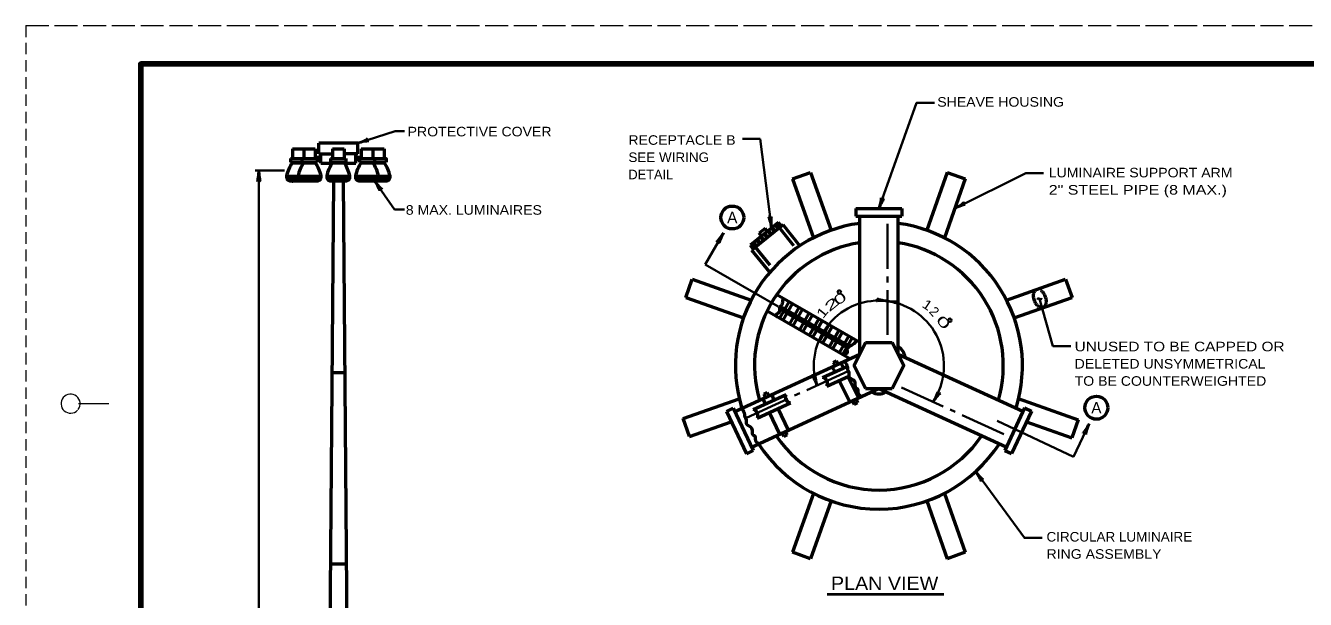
# Model space of a CAD drawing. Extents: x -1 to 679, y 0 to 440.
# Drawn here: x -1.5 to 332.8, y 289.7 to 439.6 of the extents above; entities that cross this region are included whole.
import ezdxf
from ezdxf.enums import TextEntityAlignment as Align

# ---------------------------------------------------------------- set-up
doc = ezdxf.new("R2010")
doc.units = 0
doc.header["$PDMODE"] = 32
doc.header["$PDSIZE"] = 0.5
doc.linetypes.add('LONG_DASHED', pattern=[7.5, 6, -1.5])
doc.linetypes.add('MEDIUM_DASHED', pattern=[4.5, 3, -1.5])
doc.layers.add('1', color=7, linetype='Continuous', lineweight=35)
doc.layers.add('61', color=7, linetype='Continuous', lineweight=35)

msp = doc.modelspace()

# ---------------------------------------------------------------- linework, layer by layer
at = {"layer": '1', "linetype": 'MEDIUM_DASHED', "lineweight": 13}
msp.add_line((-1.425, 439.645), (-1.485, -0.395), dxfattribs=at)
at = {"layer": '1', "lineweight": 53}
for p, q in [((75.106, 406.179), (75.106, 408.929)), ((67.696, 404.929), (71.696, 404.929)), ((67.696, 404.929), (67.696, 403.929)), ((68.196, 407.429), (71.196, 407.429)), ((68.196, 407.429), (68.196, 404.929)), ((70.696, 404.929), (74.696, 404.929)), ((70.696, 404.929), (70.696, 403.929)), ((71.196, 407.429), (74.196, 407.429)), ((71.196, 407.429), (71.196, 404.929)), ((71.196, 407.429), (71.196, 404.929)), ((74.196, 407.429), (74.196, 404.929)), ((74.696, 404.929), (74.696, 403.929)), ((75.106, 406.179), (78.696, 406.179)), ((75.606, 403.679), (75.606, 406.179)), ((78.196, 404.929), (82.196, 404.929)), ((78.196, 404.929), (78.196, 403.929)), ((78.696, 407.429), (81.696, 407.429)), ((78.696, 407.429), (78.696, 404.929)), ((81.696, 407.429), (81.696, 404.929)), ((85.285, 406.179), (81.696, 406.179)), ((82.196, 404.929), (82.196, 403.929)), ((84.785, 403.679), (84.785, 406.179)), ((85.696, 404.929), (89.696, 404.929)), ((85.696, 404.929), (85.696, 403.929)), ((86.196, 407.429), (89.196, 407.429)), ((86.196, 407.429), (86.196, 404.929)), ((89.196, 407.429), (89.196, 404.929)), ((89.196, 407.429), (92.196, 407.429)), ((89.196, 407.429), (89.196, 404.929)), ((89.696, 404.929), (89.696, 403.929)), ((92.196, 407.429), (92.196, 404.929)), ((67.696, 403.929), (71.696, 403.929)), ((68.196, 403.804), (71.196, 403.804)), ((70.696, 403.929), (74.696, 403.929)), ((71.196, 403.804), (74.196, 403.804)), ((75.606, 403.679), (78.606, 403.679)), ((78.196, 403.929), (82.196, 403.929)), ((78.696, 403.804), (81.696, 403.804)), ((81.785, 403.679), (84.785, 403.679)), ((85.696, 403.929), (89.696, 403.929)), ((86.196, 403.804), (89.196, 403.804)), ((88.696, 403.929), (92.696, 403.929)), ((89.196, 403.804), (92.196, 403.804)), ((198.868, 399.594), (203.582, 401.261)), ((203.582, 401.261), (208.916, 386.176)), ((239.249, 401.261), (233.915, 386.176)), ((239.249, 401.261), (243.963, 399.594)), ((66.321, 400.304), (72.196, 400.304)), ((67.884, 400.304), (68.38, 399.064)), ((68.696, 400.304), (69.196, 399.054)), ((69.696, 400.304), (75.196, 400.304)), ((70.196, 400.304), (70.583, 399.066)), ((70.583, 399.066), (74.696, 399.054)), ((70.884, 400.304), (71.38, 399.064)), ((71.696, 400.304), (72.196, 399.054)), ((72.196, 400.304), (73.196, 400.304)), ((72.696, 400.304), (72.696, 399.054)), ((73.696, 400.304), (73.196, 399.054)), ((74.455, 400.304), (73.956, 399.056)), ((75.196, 400.304), (74.808, 399.066)), ((75.196, 400.304), (76.071, 400.304)), ((76.821, 400.304), (77.696, 400.304)), ((78.946, 399.063), (76.946, 149.054)), ((77.696, 400.304), (78.083, 399.066)), ((77.696, 400.304), (82.696, 400.304)), ((78.083, 399.066), (82.196, 399.054)), ((78.384, 400.304), (78.88, 399.064)), ((79.196, 400.304), (79.696, 399.054)), ((80.196, 400.304), (80.196, 399.054)), ((81.196, 400.304), (80.696, 399.054)), ((81.446, 399.056), (83.446, 149.054)), ((81.955, 400.304), (81.456, 399.056)), ((82.696, 400.304), (82.308, 399.066)), ((82.696, 400.304), (83.571, 400.304)), ((84.321, 400.304), (85.196, 400.304)), ((85.196, 400.304), (85.583, 399.066)), ((85.196, 400.304), (90.696, 400.304)), ((85.583, 399.066), (89.696, 399.054)), ((85.884, 400.304), (86.358, 399.118)), ((86.696, 400.304), (87.196, 399.054)), ((87.196, 400.304), (88.196, 400.304)), ((87.696, 400.304), (87.696, 399.054)), ((88.696, 400.304), (88.196, 399.054)), ((88.196, 400.304), (93.196, 400.304)), ((88.583, 399.066), (92.696, 399.054)), ((89.455, 400.304), (88.988, 399.137)), ((90.196, 400.304), (89.808, 399.066)), ((91.696, 400.304), (91.196, 399.054)), ((92.455, 400.304), (91.988, 399.137)), ((93.196, 400.304), (92.808, 399.066)), ((93.196, 400.304), (94.071, 400.304)), ((198.868, 399.594), (204.313, 384.194)), ((243.963, 399.594), (238.518, 384.194)), ((215.415, 391.821), (227.415, 391.821)), ((215.415, 391.821), (215.416, 389.821)), ((227.415, 391.821), (227.415, 389.821)), ((195.215, 388.24), (187.832, 382.261)), ((196.002, 387.268), (195.215, 388.24)), ((215.416, 389.821), (227.415, 389.821)), ((226.416, 353.821), (226.416, 389.821)), ((196.39, 387.583), (188.23, 380.975)), ((191.671, 386.656), (190.117, 385.398)), ((190.746, 384.621), (190.117, 385.398)), ((192.3, 385.879), (191.671, 386.656)), ((199.195, 382.133), (195.419, 386.796)), ((200.796, 382.143), (196.39, 387.583)), ((188.619, 381.29), (187.832, 382.261)), ((192.977, 377.099), (189.201, 381.762)), ((192.914, 375.191), (188.23, 380.975)), ((170.975, 368.654), (172.642, 373.368)), ((172.642, 373.368), (188.042, 367.923)), ((254.788, 367.923), (270.189, 373.368)), ((270.189, 373.368), (271.856, 368.654)), ((170.975, 368.654), (186.06, 363.321)), ((216.416, 356.821), (194.715, 369.35)), ((256.771, 363.321), (271.856, 368.654)), ((213.784, 352.61), (192.205, 365.069)), ((197.92, 367.499), (195.439, 363.202)), ((198.786, 366.999), (196.305, 362.702)), ((200.518, 365.999), (198.037, 361.702)), ((201.384, 365.499), (198.903, 361.202)), ((203.116, 364.499), (200.635, 360.202)), ((203.982, 363.999), (201.501, 359.702)), ((205.714, 362.999), (203.233, 358.702)), ((206.58, 362.499), (204.099, 358.202)), ((208.312, 361.499), (205.831, 357.202)), ((209.178, 360.999), (206.697, 356.702)), ((210.91, 359.999), (208.429, 355.702)), ((211.776, 359.499), (209.295, 355.202)), ((213.508, 358.499), (211.027, 354.202)), ((214.374, 357.999), (211.893, 353.701)), ((217.916, 356.821), (224.916, 356.821)), ((183.799, 338.819), (216.416, 353.821)), ((209.464, 351.661), (210.359, 352.108)), ((209.464, 351.661), (209.886, 350.817)), ((210.359, 352.108), (210.795, 351.236)), ((211.477, 351.549), (212.148, 350.207)), ((226.416, 353.821), (259.051, 338.882)), ((78.546, 349.054), (81.846, 349.054)), ((206.695, 347.699), (213.034, 350.614)), ((207.814, 345.462), (213.548, 348.099)), ((209.241, 350.431), (209.875, 349.162)), ((213.266, 347.97), (216.07, 342.362)), ((188.169, 329.529), (221.415, 344.821)), ((210.994, 346.924), (213.834, 341.244)), ((217.916, 344.821), (224.915, 344.821)), ((221.415, 344.821), (254.698, 329.586)), ((170.273, 336.982), (184.928, 342.163)), ((188.526, 339.342), (197.157, 343.312)), ((189.59, 337.079), (198.337, 341.103)), ((191.064, 342.17), (191.706, 340.804)), ((191.317, 343.394), (192.221, 343.819)), ((191.317, 343.394), (191.749, 342.475)), ((192.221, 343.819), (192.657, 342.893)), ((193.326, 343.234), (193.977, 341.849)), ((214.479, 341.631), (214.952, 340.685)), ((215.846, 341.132), (214.952, 340.685)), ((215.388, 342.049), (215.846, 341.132)), ((257.788, 342.204), (273.505, 336.647)), ((181.564, 338.872), (183.374, 339.724)), ((181.564, 338.872), (186.785, 327.773)), ((183.374, 339.724), (188.594, 328.624)), ((192.77, 338.542), (195.433, 332.88)), ((195.041, 339.587), (197.695, 333.944)), ((259.475, 339.788), (254.274, 328.68)), ((261.287, 338.939), (256.085, 327.832)), ((259.475, 339.788), (261.287, 338.939)), ((171.94, 332.268), (170.273, 336.982)), ((171.94, 332.268), (182.855, 336.127)), ((259.971, 336.129), (271.838, 331.933)), ((273.505, 336.647), (271.838, 331.933)), ((196.118, 333.185), (196.538, 332.294)), ((197.442, 332.72), (196.538, 332.294)), ((197.027, 333.603), (197.442, 332.72)), ((186.785, 327.773), (188.594, 328.624)), ((254.274, 328.68), (256.085, 327.832)), ((204.313, 317.448), (198.868, 302.047)), ((208.916, 315.465), (203.582, 300.38)), ((233.915, 315.466), (239.249, 300.381)), ((238.518, 317.448), (243.963, 302.047)), ((203.582, 300.38), (198.868, 302.047)), ((243.963, 302.047), (239.249, 300.381)), ((78.146, 299.054), (82.246, 299.054))]:
    msp.add_line(p, q, dxfattribs=at)
at = {"layer": '1'}
for p, q in [((185.76, 410.106), (190.424, 410.106)), ((193.344, 386.91), (190.424, 410.106)), ((66.113, 401.804), (58.446, 401.804)), ((59.446, 148.054), (59.446, 401.804)), ((223.666, 376.071), (223.666, 387.821)), ((180.807, 385.484), (176.057, 377.257)), ((191.533, 383.649), (190.746, 384.621)), ((192.115, 384.121), (191.329, 385.093)), ((192.504, 384.436), (191.718, 385.407)), ((193.087, 384.908), (192.3, 385.879)), ((193.476, 385.223), (192.689, 386.194)), ((194.059, 385.695), (193.272, 386.666)), ((194.447, 386.009), (193.661, 386.981)), ((195.03, 386.481), (194.243, 387.453)), ((195.419, 386.796), (194.632, 387.768)), ((189.202, 381.762), (188.415, 382.733)), ((189.59, 382.076), (188.803, 383.048)), ((190.173, 382.548), (189.386, 383.52)), ((190.561, 382.863), (189.775, 383.834)), ((191.144, 383.335), (190.357, 384.306)), ((195.11, 366.257), (176.057, 377.257)), ((223.666, 374.071), (223.666, 372.571)), ((223.666, 358.821), (223.666, 370.571)), ((202.587, 344.433), (213.39, 349.402)), ((227.313, 345.146), (238.179, 340.172)), ((186.787, 337.166), (197.59, 342.135)), ((199.407, 342.971), (200.77, 343.597)), ((239.997, 339.339), (241.361, 338.715)), ((243.179, 337.882), (254.046, 332.909)), ((252.346, 336.354), (272.27, 327.024)), ((276.299, 335.628), (272.27, 327.024))]:
    msp.add_line(p, q, dxfattribs=at)
at = {"layer": '1', "lineweight": 106}
for p, q in [((75.606, 404.929), (74.696, 404.929)), ((84.785, 404.929), (85.696, 404.929))]:
    msp.add_line(p, q, dxfattribs=at)
at = {"layer": '1', "lineweight": 200}
msp.add_line((195.631, 365.956), (213.41, 355.691), dxfattribs=at)
at = {"layer": '1', "lineweight": 40}
msp.add_line((207.899, 291.106), (238.388, 291.106), dxfattribs=at)
at = {"layer": '1'}
for points in [[(221.415, 391.821), (231.273, 419.49), (235.936, 419.49)], [(85.285, 408.929), (95.027, 412.036), (97.483, 412.036)], [(89.696, 399.054), (94.903, 391.61), (97.451, 391.61)], [(241.24, 391.894), (259.769, 401.117), (264.432, 401.117)], [(263.365, 368.261), (266.858, 355.942), (271.521, 355.942)], [(246.702, 323.129), (259.408, 305.817), (264.071, 305.817)]]:
    msp.add_lwpolyline(points, dxfattribs=at)
at = {"layer": '1', "lineweight": 53}
for points in [[(85.285, 406.179), (85.285, 408.929), (75.106, 408.929)], [(88.696, 404.929), (92.696, 404.929), (92.696, 403.929)], [(67.196, 400.304), (67.583, 399.066), (71.696, 399.054)], [(216.416, 353.821), (216.416, 387.986), (216.416, 389.821)], [(217.916, 356.821), (214.916, 350.821), (217.916, 344.821)], [(224.915, 344.821), (227.915, 350.821), (224.916, 356.821)]]:
    msp.add_lwpolyline(points, dxfattribs=at)
for centre in [(183.109, 389.517), (278.22, 339.813)]:
    msp.add_circle(centre, 3, dxfattribs=at)
at = {"layer": '1'}
for centre in [(211.087, 370.039), (239.939, 362.669)]:
    msp.add_circle(centre, 0.45, dxfattribs=at)
at = {"layer": '1', "lineweight": 53}
for centre, radius, start, end in [((75.102, 398.772), 8.545, 143.92712, 169.6757), ((78.102, 398.772), 8.545, 143.92712, 169.6757), ((67.289, 398.772), 8.545, 10.3243, 36.07288), ((85.602, 398.772), 8.545, 143.92712, 169.6757), ((74.789, 398.772), 8.545, 10.3243, 36.07288), ((93.102, 398.772), 8.545, 143.92712, 169.6757), ((82.289, 398.772), 8.545, 10.3243, 36.07288), ((85.289, 398.772), 8.545, 10.3243, 36.07288), ((67.758, 400.128), 1.077, 170.6394, 266.68021), ((70.758, 400.128), 1.077, 170.6394, 266.68021), ((74.633, 400.128), 1.077, 273.31979, 9.3606), ((78.258, 400.128), 1.077, 170.6394, 260.64075), ((82.133, 400.128), 1.077, 273.31979, 9.3606), ((85.758, 400.128), 1.077, 170.6394, 266.68021), ((89.633, 400.128), 1.077, 273.31979, 9.3606), ((92.633, 400.128), 1.077, 273.31979, 9.3606), ((221.415, 350.821), 37.5, 97.66187, 197.32332), ((221.415, 350.821), 37.5, 342.77204, 82.33736), ((221.415, 350.821), 32.5, 98.84944, 196.18056), ((221.415, 350.821), 32.5, 343.91337, 81.14967), ((224.68, 352.706), 3.565, 4.53272, 60.86921), ((206.501, 346.226), 1.486, 327.89377, 82.48428), ((198.452, 342.584), 1.486, 150.66912, 265.55469), ((221.414, 346.606), 3.188, 235.2883, 304.81151), ((188.332, 337.869), 1.486, 327.89377, 82.48428), ((221.415, 350.821), 32.5, 214.35563, 325.74061), ((221.415, 350.821), 37.5, 213.05829, 327.03907)]:
    msp.add_arc(centre, radius, start, end, dxfattribs=at)
at = {"layer": '1'}
for centre, radius, start, end in [((221.415, 350.821), 17, 82.39357, 197.72393), ((263.122, 367.999), 0.357, 47.242, 165.78449), ((263.607, 368.523), 0.357, 227.242, 345.78449), ((221.415, 350.821), 17, 326.24589, 82.39357)]:
    msp.add_arc(centre, radius, start, end, dxfattribs=at)
at = {"layer": '1', "lineweight": 40}
for centre, major_axis, ratio, start_param, end_param in [((86.241, 409.523), (-1.654, -0.691), 0.122415, 0.8963533, 3.1415927), ((86.417, 409.067), (-1.727, -0.366), 0.07063, 3.1407148, 5.41811), ((59.234, 400.683), (0.176, 1.756), 0.07063, 3.1407148, 5.41811), ((59.722, 400.712), (-0.156, 1.786), 0.122415, 0.8963533, 3.1415927), ((90.165, 398.014), (0.863, -1.54), 0.07063, 6.2823074, 8.5597026), ((90.548, 398.318), (-1.151, 1.374), 0.122415, 0.8963533, 3.1415927), ((221.521, 392.941), (-0.452, -1.735), 0.122415, 0.8963533, 3.1415927), ((221.521, 392.941), (-0.452, -1.735), 0.122415, 0.8963533, 3.1415927), ((221.991, 392.805), (-0.755, -1.596), 0.07063, 3.1407148, 5.41811), ((221.991, 392.805), (-0.755, -1.596), 0.07063, 3.1407148, 5.41811), ((242.094, 392.628), (-1.529, -0.935), 0.122415, 0.8963533, 3.1415927), ((242.094, 392.628), (-1.529, -0.935), 0.122415, 0.8963533, 3.1415927), ((242.338, 392.204), (1.651, 0.625), 0.07063, 6.2823074, 8.5597026), ((242.338, 392.204), (1.651, 0.625), 0.07063, 6.2823074, 8.5597026), ((192.933, 387.958), (0.378, -1.752), 0.122415, 0.8963533, 3.1415927), ((192.933, 387.958), (0.378, -1.752), 0.122415, 0.8963533, 3.1415927), ((193.414, 388.048), (-0.045, 1.765), 0.07063, 6.2823074, 8.5597026), ((193.414, 388.048), (-0.045, 1.765), 0.07063, 6.2823074, 8.5597026), ((180.064, 384.619), (1.03, 1.433), 0.07063, 3.1407148, 5.41811), ((180.064, 384.619), (1.03, 1.433), 0.07063, 3.1407148, 5.41811), ((180.501, 384.401), (0.758, 1.625), 0.122415, 0.8963533, 3.1415927), ((180.501, 384.401), (0.758, 1.625), 0.122415, 0.8963533, 3.1415927), ((222.547, 367.542), (1.791, -0.082), 0.122415, 0.8963533, 3.1415927), ((222.547, 367.542), (1.791, -0.082), 0.122415, 0.8963533, 3.1415927), ((222.583, 368.029), (-1.718, 0.407), 0.07063, 6.2823074, 8.5597026), ((222.583, 368.029), (-1.718, 0.407), 0.07063, 6.2823074, 8.5597026), ((224.748, 367.313), (1.718, -0.407), 0.07063, 6.2823074, 8.5597026), ((224.748, 367.313), (1.718, -0.407), 0.07063, 6.2823074, 8.5597026), ((224.784, 367.801), (-1.791, 0.082), 0.122415, 0.8963533, 3.1415927), ((224.784, 367.801), (-1.791, 0.082), 0.122415, 0.8963533, 3.1415927), ((204.627, 346.601), (0.692, -1.653), 0.122415, 0.8963533, 3.1415927), ((205.083, 346.777), (0.367, -1.727), 0.07063, 3.1407148, 5.41811), ((235.926, 342.436), (-0.862, -1.571), 0.122415, 0.8963533, 3.1415927), ((236.348, 342.189), (1.122, 1.363), 0.07063, 6.2823074, 8.5597026), ((275.632, 334.703), (0.904, 1.516), 0.07063, 3.1407148, 5.41811), ((276.086, 334.522), (0.616, 1.683), 0.122415, 0.8963533, 3.1415927), ((247.194, 322.101), (-0.898, 1.52), 0.07063, 3.1407148, 5.41811), ((247.57, 322.413), (-1.182, 1.347), 0.122415, 0.8963533, 3.1415927)]:
    msp.add_ellipse(centre, major_axis=major_axis, ratio=ratio, start_param=start_param, end_param=end_param, dxfattribs=at)
at = {"layer": '1', "linetype": 'LONG_DASHED', "lineweight": 53}
msp.add_ellipse((263.44, 368.331), major_axis=(0.833, -2.357), ratio=0.599999, dxfattribs=at)
at = {"layer": '1', "lineweight": 53}
for points in [[(196.447, 368.35), (196.234, 367.703), (196.007, 366.626), (195.469, 365.917), (195.469, 365.067), (195.044, 364.472), (194.534, 363.962), (194.803, 363.569)], [(215.549, 357.321), (214.902, 356.51), (213.684, 355.773), (213.06, 355.065), (213.089, 354.158), (212.052, 353.61)], [(212.457, 351.952), (213.168, 350.303), (213.25, 349.729), (213.537, 349.237), (213.578, 348.007), (215.012, 346.737), (215.422, 344.974), (215.832, 344.728), (215.914, 343.908), (216.827, 342.662)], [(185.616, 339.655), (186.327, 338.005), (186.409, 337.432), (186.696, 336.94), (186.737, 335.71), (188.171, 334.439), (188.581, 332.677), (188.991, 332.431), (189.073, 331.611), (189.986, 330.365)]]:
    msp.add_spline(points, degree=3, dxfattribs=at)
at = {"layer": '1'}
msp.add_point((68.196, 399.054), dxfattribs=at)
at = {"layer": '61', "linetype": 'LONG_DASHED', "lineweight": 13}
msp.add_line((-1.425, 439.645), (678.595, 439.645), dxfattribs=at)
at = {"layer": '61', "lineweight": 13}
msp.add_line((12.295, 340.885), (20.275, 340.905), dxfattribs=at)
at = {"layer": '61', "lineweight": 158}
msp.add_lwpolyline([(667.615, 429.645), (28.575, 429.645), (28.575, 9.625)], dxfattribs=at)
at = {"layer": '61', "lineweight": 13}
msp.add_arc((10.273, 340.887), 2.5, 323.13009, 316.23216, dxfattribs=at)

# ---------------------------------------------------------------- texts
at = {"layer": '1', "width": 1.1}
for s, height, p in [('SHEAVE HOUSING', 2.5, (253.212, 418.453)), ('PROTECTIVE COVER', 2.5, (117.103, 410.703)), ('8 MAX. LUMINAIRES', 2.5, (115.612, 390.236)), ('PLAN VIEW', 3.5, (222.905, 292.209))]:
    msp.add_text(s, height=height, dxfattribs=at).set_placement(p, align=Align.CENTER)
at = {"layer": '1'}
for s, width, p in [('RECEPTACLE B', 1.1, (155.982, 408.501)), ('SEE WIRING', 1.05, (155.982, 404.001)), ('LUMINAIRE SUPPORT ARM', 1.1, (265.777, 399.993)), ('2" STEEL PIPE (8 MAX.)', 1.25, (265.777, 395.493)), ('UNUSED TO BE CAPPED OR', 1.2, (272.543, 354.552)), ('DELETED UNSYMMETRICAL', 1.1, (272.543, 350.052)), ('TO BE COUNTERWEIGHTED', 1.1, (272.543, 345.552)), ('CIRCULAR LUMINAIRE', 1.05, (265.197, 304.858)), ('RING ASSEMBLY', 1.1, (265.197, 300.358))]:
    msp.add_text(s, height=2.5, dxfattribs=dict(at, width=width)).set_placement(p)
msp.add_text('DETAIL', height=2.5, dxfattribs=at).set_placement((155.982, 399.501))
for p in [(183.109, 388.017), (278.22, 338.313)]:
    msp.add_text('A', height=3, dxfattribs=at).set_placement(p, align=Align.CENTER)
for s, rotation, width, p in [('2', 39.009, 1.95, (209.837, 365.861)), ('0', 32.793, 1.75, (211.911, 367.27)), ('1', 326.369, 1.2, (233.383, 365.649)), ('1', 51.44, 1.4, (207.6, 363.931)), ('0', 307.723, 1.9, (237.255, 361.357))]:
    msp.add_text(s, height=2.5, rotation=rotation, dxfattribs=dict(at, width=width)).set_placement(p, align=Align.CENTER)
msp.add_text('2', height=2.5, rotation=313.938, dxfattribs=at).set_placement((234.972, 364.099), align=Align.CENTER)

doc.saveas('drawing.dxf')
